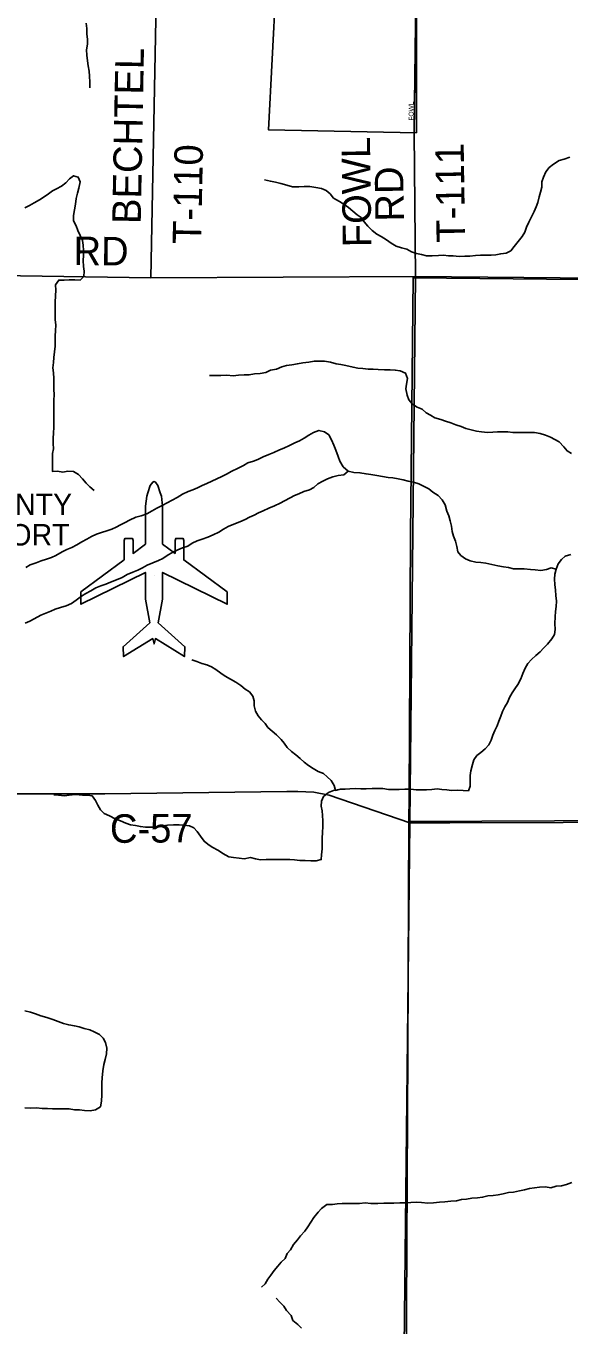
# Model space of a CAD drawing. Extents: x 1857828 to 2277390, y 930619 to 1324581.
# Drawn here: x 2056259 to 2061968, y 1210395 to 1224059 of the extents above; entities that cross this region are included whole.
import ezdxf

# ---------------------------------------------------------------- set-up
doc = ezdxf.new("R2010")
doc.units = 0
for name, color, linetype in [('GM_X_Airport_Class_2', 7, 'Continuous'), ('GM_X_Airport_Location_Class_2', 7, 'Continuous'), ('GM_X_Airport_Text_Class_2', 7, 'Continuous'), ('GM_X_City_Street', 7, 'Continuous'), ('GM_X_City_Street_Text', 7, 'Continuous'), ('GM_X_Corporation', 7, 'Continuous'), ('GM_X_County_Road', 7, 'Continuous'), ('GM_X_County_Road_Text', 7, 'Continuous'), ('GM_X_Minor_River', 7, 'Continuous'), ('GM_X_Section', 7, 'Continuous'), ('GM_X_Township', 7, 'Continuous'), ('GM_X_Township_Road', 7, 'Continuous'), ('GM_X_Township_Road_Text', 7, 'Continuous')]:
    doc.layers.add(name, color=color, linetype=linetype)

msp = doc.modelspace()

# ---------------------------------------------------------------- linework, layer by layer
at = {"layer": 'GM_X_Airport_Class_2'}
msp.add_lwpolyline([(2057292, 1218448), (2056836, 1218111), (2056836, 1217981), (2057515, 1218316), (2057515, 1218034), (2057560, 1217785), (2057280, 1217534), (2057285, 1217431), (2057591, 1217620), (2057605, 1217565), (2057619, 1217620), (2057925, 1217431), (2057929, 1217534), (2057650, 1217785), (2057695, 1218034), (2057695, 1218316), (2058374, 1217981), (2058374, 1218111), (2057918, 1218448), (2057918, 1218650), (2057911, 1218674), (2057833, 1218674), (2057826, 1218650), (2057826, 1218516), (2057695, 1218613), (2057695, 1218613), (2057695, 1219011), (2057682, 1219116), (2057671, 1219153), (2057644, 1219230), (2057619, 1219264), (2057605, 1219270), (2057591, 1219264), (2057566, 1219230), (2057539, 1219153), (2057528, 1219116), (2057515, 1219011), (2057515, 1218613), (2057384, 1218516), (2057384, 1218650), (2057377, 1218674), (2057299, 1218674), (2057292, 1218650)], close=True, dxfattribs=at)
at = {"layer": 'GM_X_Airport_Location_Class_2'}
msp.add_line((2057605, 1218287), (2057605, 1218287), dxfattribs=at)
at = {"layer": 'GM_X_City_Street'}
msp.add_lwpolyline([(2060339, 1222974), (2060377, 1225997), (2060390, 1226015)], dxfattribs=at)
at = {"layer": 'GM_X_Corporation'}
msp.add_lwpolyline([(2060364, 1224534), (2060364, 1222938), (2058808, 1222969), (2058885, 1224457)], dxfattribs=at)
at = {"layer": 'GM_X_County_Road'}
for points in [[(2052543, 1221491), (2057571, 1221413), (2060354, 1221425)], [(2060354, 1221425), (2063013, 1221403)], [(2046506, 1216127), (2048640, 1216054), (2049006, 1216051), (2049292, 1216047), (2049598, 1216044), (2049915, 1216043), (2050453, 1216041), (2050976, 1216041), (2052033, 1216054), (2055846, 1215989), (2056808, 1215987), (2057088, 1215987), (2059001, 1216013), (2059118, 1216013), (2059284, 1216005), (2059445, 1215973), (2060294, 1215683), (2060319, 1215683)], [(2060319, 1215683), (2060715, 1215683), (2064289, 1215694), (2067474, 1215668), (2070111, 1215714), (2071694, 1215684), (2072330, 1215682)]]:
    msp.add_lwpolyline(points, dxfattribs=at)
at = {"layer": 'GM_X_Minor_River'}
for points in [[(2056893, 1224089), (2056900, 1224033), (2056900, 1223972), (2056904, 1223922), (2056904, 1223868), (2056896, 1223808), (2056900, 1223752), (2056906, 1223692), (2056914, 1223642), (2056923, 1223584), (2056927, 1223533), (2056929, 1223469), (2056931, 1223409)], [(2061976, 1222680), (2061918, 1222661), (2061864, 1222645), (2061806, 1222607), (2061758, 1222571), (2061725, 1222525), (2061699, 1222469), (2061683, 1222421), (2061681, 1222365), (2061668, 1222313), (2061654, 1222263), (2061640, 1222205), (2061624, 1222157), (2061600, 1222111), (2061577, 1222061), (2061547, 1221999), (2061521, 1221943), (2061503, 1221891), (2061474, 1221847), (2061432, 1221793), (2061392, 1221743), (2061356, 1221697), (2061306, 1221671), (2061250, 1221665), (2061200, 1221655), (2061150, 1221652), (2061100, 1221650), (2061038, 1221652), (2060984, 1221648), (2060924, 1221641), (2060872, 1221639), (2060814, 1221637), (2060750, 1221642), (2060700, 1221644), (2060648, 1221652), (2060596, 1221648), (2060530, 1221645), (2060468, 1221645), (2060416, 1221657), (2060364, 1221669), (2060312, 1221686)], [(2056246, 1222148), (2056296, 1222171), (2056346, 1222199), (2056400, 1222231), (2056450, 1222265), (2056494, 1222295), (2056536, 1222325), (2056580, 1222349), (2056631, 1222376), (2056677, 1222412), (2056717, 1222452), (2056759, 1222486), (2056809, 1222472), (2056829, 1222420), (2056816, 1222355), (2056802, 1222303), (2056788, 1222247), (2056778, 1222187), (2056767, 1222127), (2056757, 1222067), (2056757, 1222011), (2056785, 1221959), (2056805, 1221910), (2056830, 1221856), (2056852, 1221806), (2056860, 1221756), (2056862, 1221698), (2056863, 1221648), (2056859, 1221593), (2056863, 1221533), (2056869, 1221481), (2056867, 1221427), (2056828, 1221389), (2056774, 1221391), (2056714, 1221390), (2056660, 1221386), (2056604, 1221388), (2056570, 1221340), (2056572, 1221282), (2056568, 1221224), (2056565, 1221158), (2056565, 1221100), (2056567, 1221033), (2056567, 1220971), (2056572, 1220919), (2056570, 1220855), (2056564, 1220801), (2056566, 1220749), (2056565, 1220693), (2056559, 1220633), (2056553, 1220574), (2056547, 1220524), (2056540, 1220466), (2056548, 1220412), (2056550, 1220354), (2056552, 1220302), (2056550, 1220240), (2056555, 1220185), (2056551, 1220123), (2056551, 1220069), (2056553, 1220011), (2056552, 1219957), (2056550, 1219893), (2056550, 1219839), (2056548, 1219783), (2056543, 1219722)], [(2060312, 1221686), (2060264, 1221712), (2060206, 1221728), (2060150, 1221745), (2060098, 1221777), (2060048, 1221813), (2059992, 1221846), (2059949, 1221872), (2059897, 1221910), (2059853, 1221954), (2059815, 1222001), (2059783, 1222045), (2059739, 1222073), (2059694, 1222112), (2059650, 1222152), (2059604, 1222182), (2059556, 1222216), (2059492, 1222251), (2059458, 1222295), (2059416, 1222331), (2059365, 1222352), (2059307, 1222360), (2059243, 1222372), (2059185, 1222371), (2059129, 1222369), (2059061, 1222369), (2059001, 1222387), (2058937, 1222402), (2058881, 1222416), (2058829, 1222428), (2058767, 1222443)], [(2061995, 1219565), (2061947, 1219593), (2061913, 1219635), (2061863, 1219688), (2061818, 1219714), (2061774, 1219738), (2061722, 1219759), (2061666, 1219775), (2061604, 1219787), (2061548, 1219787), (2061494, 1219788), (2061438, 1219788), (2061378, 1219786), (2061326, 1219792), (2061274, 1219793), (2061216, 1219795), (2061166, 1219791), (2061110, 1219787), (2061048, 1219792), (2060996, 1219800), (2060940, 1219814), (2060882, 1219829), (2060834, 1219849), (2060778, 1219867), (2060726, 1219887), (2060670, 1219906), (2060622, 1219924), (2060558, 1219940), (2060513, 1219967), (2060465, 1219993), (2060423, 1220033), (2060373, 1220053), (2060323, 1220086), (2060285, 1220130), (2060265, 1220180), (2060254, 1220244), (2060258, 1220295), (2060270, 1220353), (2060248, 1220411), (2060194, 1220433), (2060141, 1220443), (2060087, 1220446), (2060027, 1220446), (2059963, 1220450), (2059909, 1220451), (2059855, 1220453), (2059799, 1220459), (2059749, 1220463), (2059697, 1220472), (2059621, 1220492), (2059569, 1220500), (2059519, 1220509), (2059459, 1220525), (2059397, 1220537), (2059345, 1220537), (2059289, 1220536), (2059231, 1220526), (2059171, 1220518), (2059113, 1220510), (2059055, 1220499), (2058997, 1220489), (2058947, 1220475), (2058893, 1220453), (2058830, 1220440), (2058782, 1220418), (2058720, 1220406), (2058660, 1220402), (2058606, 1220394), (2058554, 1220393), (2058494, 1220389), (2058436, 1220383), (2058370, 1220388), (2058306, 1220386), (2058238, 1220386), (2058188, 1220384)], [(2059646, 1219381), (2059592, 1219426), (2059560, 1219486), (2059541, 1219536), (2059517, 1219600), (2059497, 1219655), (2059471, 1219709), (2059442, 1219761), (2059396, 1219793), (2059338, 1219808), (2059282, 1219786), (2059234, 1219758), (2059183, 1219726), (2059133, 1219698), (2059085, 1219677), (2059029, 1219651), (2058971, 1219623), (2058923, 1219605), (2058863, 1219577), (2058811, 1219554), (2058751, 1219530), (2058698, 1219504), (2058650, 1219484), (2058592, 1219468), (2058544, 1219438), (2058484, 1219409), (2058422, 1219379), (2058368, 1219349), (2058318, 1219325), (2058266, 1219299), (2058212, 1219274), (2058159, 1219250), (2058111, 1219228), (2058063, 1219206), (2058013, 1219184), (2057965, 1219165), (2057905, 1219139), (2057847, 1219105), (2057795, 1219077), (2057743, 1219049), (2057690, 1219019), (2057636, 1218992), (2057586, 1218962), (2057528, 1218932), (2057468, 1218912), (2057412, 1218898), (2057346, 1218865), (2057300, 1218841), (2057252, 1218817), (2057207, 1218793), (2057161, 1218771), (2057107, 1218752), (2057053, 1218736), (2056999, 1218718), (2056947, 1218692), (2056899, 1218664), (2056847, 1218636), (2056793, 1218607), (2056739, 1218579), (2056688, 1218557), (2056638, 1218531), (2056574, 1218495), (2056526, 1218472), (2056476, 1218454), (2056420, 1218436), (2056366, 1218418), (2056302, 1218396), (2056258, 1218367)], [(2056543, 1219722), (2056543, 1219670), (2056547, 1219616), (2056537, 1219566), (2056538, 1219508), (2056538, 1219440), (2056538, 1219376), (2056590, 1219379), (2056646, 1219371), (2056700, 1219381), (2056758, 1219377), (2056810, 1219346), (2056852, 1219298), (2056891, 1219254), (2056929, 1219215), (2056977, 1219177)], [(2059646, 1219381), (2059602, 1219341), (2059542, 1219336), (2059484, 1219320), (2059430, 1219298), (2059378, 1219276), (2059327, 1219246), (2059285, 1219209), (2059239, 1219183), (2059181, 1219165), (2059127, 1219143), (2059081, 1219123), (2059035, 1219099), (2058977, 1219068), (2058931, 1219044), (2058872, 1219016), (2058812, 1218990), (2058754, 1218964), (2058704, 1218941), (2058658, 1218919), (2058610, 1218895), (2058562, 1218871), (2058506, 1218847), (2058444, 1218824), (2058386, 1218798), (2058337, 1218770), (2058285, 1218738), (2058227, 1218710), (2058169, 1218686), (2058111, 1218667), (2058057, 1218647), (2058005, 1218623), (2057959, 1218593), (2057905, 1218573), (2057856, 1218552), (2057804, 1218528), (2057744, 1218494), (2057698, 1218462), (2057652, 1218442), (2057592, 1218418), (2057534, 1218393), (2057482, 1218365), (2057434, 1218339), (2057381, 1218317), (2057323, 1218293), (2057269, 1218264), (2057209, 1218238), (2057149, 1218212), (2057097, 1218194), (2057047, 1218174), (2056993, 1218153), (2056941, 1218123), (2056887, 1218093), (2056842, 1218067), (2056786, 1218025), (2056736, 1217989), (2056680, 1217964), (2056622, 1217948), (2056566, 1217930), (2056520, 1217908), (2056466, 1217888), (2056416, 1217867), (2056345, 1217829), (2056299, 1217805), (2056249, 1217783)], [(2061832, 1218349), (2061782, 1218363), (2061732, 1218347), (2061672, 1218337), (2061612, 1218342), (2061562, 1218348), (2061498, 1218352), (2061446, 1218354), (2061384, 1218355), (2061330, 1218369), (2061278, 1218375), (2061218, 1218386), (2061158, 1218398), (2061092, 1218414), (2061040, 1218419), (2060990, 1218425), (2060928, 1218439), (2060878, 1218459), (2060832, 1218492), (2060798, 1218532), (2060787, 1218590), (2060773, 1218646), (2060755, 1218696), (2060739, 1218745), (2060732, 1218801), (2060718, 1218859), (2060704, 1218911), (2060682, 1218961), (2060665, 1219026), (2060635, 1219078), (2060591, 1219126), (2060535, 1219161), (2060493, 1219195), (2060439, 1219223), (2060389, 1219247), (2060334, 1219266), (2060278, 1219276), (2060224, 1219290), (2060170, 1219301), (2060116, 1219309), (2060066, 1219315), (2060008, 1219323), (2059946, 1219336), (2059884, 1219344), (2059834, 1219352), (2059770, 1219363), (2059704, 1219367), (2059646, 1219381)], [(2061986, 1218504), (2061928, 1218487), (2061890, 1218453), (2061854, 1218407), (2061832, 1218349), (2061818, 1218297), (2061817, 1218244), (2061819, 1218190), (2061825, 1218130), (2061829, 1218074), (2061836, 1218012), (2061832, 1217956), (2061826, 1217904), (2061824, 1217850), (2061819, 1217779), (2061823, 1217715), (2061815, 1217663), (2061789, 1217619), (2061742, 1217561), (2061700, 1217519), (2061664, 1217481), (2061618, 1217442), (2061572, 1217402), (2061534, 1217360), (2061507, 1217310), (2061483, 1217252), (2061461, 1217196), (2061431, 1217138), (2061398, 1217092), (2061370, 1217050), (2061342, 1217000), (2061320, 1216950), (2061294, 1216904), (2061267, 1216854), (2061251, 1216804), (2061231, 1216752), (2061211, 1216704), (2061189, 1216656), (2061168, 1216604), (2061150, 1216552), (2061126, 1216504), (2061086, 1216460), (2061040, 1216424), (2060999, 1216390), (2060969, 1216346), (2060953, 1216298), (2060937, 1216232), (2060929, 1216180), (2060930, 1216120), (2060930, 1216069), (2060910, 1216021), (2060856, 1216022), (2060796, 1216026), (2060732, 1216024), (2060682, 1216029), (2060632, 1216035), (2060582, 1216041), (2060524, 1216033), (2060470, 1216032), (2060416, 1216032), (2060362, 1216032), (2060306, 1216038), (2060242, 1216039), (2060182, 1216035), (2060126, 1216033), (2060070, 1216035), (2060010, 1216044), (2059958, 1216046), (2059900, 1216046), (2059836, 1216042), (2059778, 1216041), (2059724, 1216043), (2059664, 1216041), (2059614, 1216038), (2059564, 1216036)], [(2059564, 1216036), (2059514, 1216024), (2059500, 1216076), (2059466, 1216128), (2059424, 1216169), (2059385, 1216201), (2059331, 1216225), (2059279, 1216254), (2059229, 1216286), (2059183, 1216322), (2059143, 1216360), (2059095, 1216399), (2059050, 1216435), (2059006, 1216475), (2058974, 1216522), (2058940, 1216560), (2058894, 1216608), (2058848, 1216648), (2058803, 1216687), (2058773, 1216727), (2058735, 1216765), (2058701, 1216808), (2058673, 1216858), (2058658, 1216914), (2058656, 1216966), (2058644, 1217016), (2058608, 1217059), (2058564, 1217089), (2058516, 1217127), (2058465, 1217163), (2058409, 1217194), (2058353, 1217224), (2058309, 1217256), (2058255, 1217295), (2058209, 1217323), (2058161, 1217343), (2058107, 1217360), (2058056, 1217380), (2058002, 1217398)], [(2059564, 1216036), (2059492, 1216022), (2059438, 1216004), (2059388, 1215962), (2059365, 1215912), (2059363, 1215860), (2059373, 1215810), (2059377, 1215760), (2059379, 1215704), (2059380, 1215644), (2059376, 1215582), (2059374, 1215523), (2059374, 1215469), (2059373, 1215409), (2059365, 1215347), (2059363, 1215297), (2059311, 1215283), (2059255, 1215283), (2059195, 1215288), (2059139, 1215288), (2059083, 1215294), (2059033, 1215298), (2058969, 1215297), (2058909, 1215297), (2058847, 1215297), (2058783, 1215298), (2058723, 1215296), (2058673, 1215306), (2058619, 1215318), (2058553, 1215307), (2058501, 1215313), (2058441, 1215321), (2058391, 1215327), (2058329, 1215360), (2058281, 1215394), (2058217, 1215429), (2058171, 1215461), (2058132, 1215491), (2058094, 1215543), (2058060, 1215594), (2058024, 1215630), (2057978, 1215654), (2057918, 1215660), (2057868, 1215663), (2057810, 1215663), (2057746, 1215659), (2057686, 1215648), (2057630, 1215638), (2057574, 1215638), (2057514, 1215640), (2057462, 1215645), (2057410, 1215655), (2057358, 1215663), (2057310, 1215679), (2057254, 1215706), (2057195, 1215726), (2057135, 1215756), (2057079, 1215783), (2057043, 1215819), (2057013, 1215871), (2056991, 1215917), (2056956, 1215966), (2056906, 1215974), (2056852, 1215976), (2056778, 1215980), (2056714, 1215975), (2056662, 1215969), (2056602, 1215975), (2056550, 1215978)], [(2056246, 1212689), (2056308, 1212685), (2056368, 1212687), (2056430, 1212682), (2056484, 1212682), (2056538, 1212678), (2056598, 1212678), (2056660, 1212677), (2056714, 1212677), (2056768, 1212669), (2056820, 1212667), (2056874, 1212660), (2056932, 1212658), (2056990, 1212668), (2057042, 1212700), (2057052, 1212758), (2057056, 1212824), (2057057, 1212886), (2057055, 1212952), (2057059, 1213002), (2057065, 1213078), (2057078, 1213142), (2057092, 1213197), (2057104, 1213257), (2057108, 1213317), (2057093, 1213375), (2057071, 1213421), (2057033, 1213459), (2056977, 1213486), (2056929, 1213508), (2056871, 1213522), (2056817, 1213541), (2056767, 1213549), (2056709, 1213559), (2056654, 1213573), (2056596, 1213594), (2056540, 1213616), (2056478, 1213638), (2056416, 1213657), (2056360, 1213675), (2056306, 1213693), (2056248, 1213708)], [(2061997, 1211903), (2061941, 1211883), (2061888, 1211867), (2061834, 1211865), (2061776, 1211848), (2061720, 1211858), (2061656, 1211856), (2061606, 1211848), (2061552, 1211839)], [(2061552, 1211839), (2061500, 1211827), (2061446, 1211815), (2061386, 1211803), (2061330, 1211798), (2061274, 1211784), (2061222, 1211774), (2061172, 1211768), (2061116, 1211763), (2061060, 1211749), (2061006, 1211743), (2060946, 1211739), (2060890, 1211730), (2060836, 1211724), (2060786, 1211710), (2060724, 1211706), (2060664, 1211701), (2060608, 1211697), (2060542, 1211691), (2060484, 1211687), (2060416, 1211694), (2060364, 1211696), (2060304, 1211694), (2060246, 1211690), (2060190, 1211689), (2060126, 1211687), (2060074, 1211687), (2060022, 1211685), (2059958, 1211684), (2059886, 1211682), (2059826, 1211690), (2059764, 1211683), (2059708, 1211683), (2059638, 1211683), (2059582, 1211683), (2059532, 1211680), (2059482, 1211672), (2059420, 1211672), (2059365, 1211630), (2059331, 1211592), (2059285, 1211535), (2059255, 1211487), (2059223, 1211437), (2059190, 1211393), (2059146, 1211343), (2059112, 1211301), (2059072, 1211253), (2059038, 1211197), (2059005, 1211157), (2058983, 1211103), (2058943, 1211067), (2058905, 1211023), (2058867, 1210977), (2058832, 1210931), (2058802, 1210887), (2058772, 1210839), (2058734, 1210803)], [(2059156, 1210372), (2059118, 1210411), (2059064, 1210453), (2059047, 1210505), (2058999, 1210558), (2058969, 1210602), (2058927, 1210644), (2058889, 1210688)]]:
    msp.add_lwpolyline(points, dxfattribs=at)
at = {"layer": 'GM_X_Section'}
for points in [[(2065236, 1221364), (2065718, 1221358), (2065650, 1215721), (2060285, 1215697), (2060286, 1215959), (2060300, 1218715), (2060328, 1221413)], [(2060285, 1215697), (2065650, 1215721), (2065594, 1209969), (2060255, 1209971), (2060255, 1209988), (2060259, 1210570), (2060274, 1213273)]]:
    msp.add_lwpolyline(points, close=True, dxfattribs=at)
at = {"layer": 'GM_X_Township'}
for points in [[(2060647, 1243760), (2060635, 1243186), (2060633, 1243086), (2060628, 1242873), (2060601, 1241567), (2060572, 1240155), (2060516, 1235516), (2060506, 1234916), (2060504, 1234835), (2060494, 1234234), (2060445, 1231137), (2060427, 1229155), (2060377, 1225997), (2060339, 1222935), (2060354, 1221425), (2057571, 1221413), (2052543, 1221491), (2047129, 1221472), (2042623, 1221498), (2039744, 1221515), (2035913, 1221537)], [(2086907, 1225123), (2086885, 1221291), (2086459, 1221291), (2084361, 1221334), (2078877, 1221358), (2077897, 1221356), (2076980, 1221348), (2076348, 1221342), (2075410, 1221333), (2074869, 1221327), (2074729, 1221326), (2072926, 1221321), (2071560, 1221318), (2067771, 1221365), (2063493, 1221407), (2063013, 1221403), (2060354, 1221425), (2060339, 1222935), (2060377, 1225997)], [(2032548, 1208287), (2032612, 1216299), (2032643, 1220072), (2032655, 1221559), (2034660, 1221545), (2035913, 1221537), (2039744, 1221515), (2042623, 1221498), (2047129, 1221472), (2052543, 1221491), (2057571, 1221413), (2060354, 1221425), (2060294, 1215683), (2060204, 1207259)], [(2060204, 1207259), (2060294, 1215683), (2060354, 1221425), (2063013, 1221403), (2063493, 1221407), (2067771, 1221365), (2071560, 1221318)]]:
    msp.add_lwpolyline(points, dxfattribs=at)
at = {"layer": 'GM_X_Township_Road'}
for points in [[(2057571, 1221413), (2057697, 1227931)], [(2060354, 1221425), (2060339, 1222935), (2060339, 1222974)]]:
    msp.add_lwpolyline(points, dxfattribs=at)

# ---------------------------------------------------------------- texts
at = {"layer": 'GM_X_Airport_Text_Class_2'}
for s, p in [('LORAIN COUNTY', (2054270, 1218920)), ('REGIONAL AIRPORT', (2053742, 1218599))]:
    msp.add_text(s, height=225, rotation=0, dxfattribs=at).set_placement(p)
at = {"layer": 'GM_X_City_Street_Text'}
msp.add_text('FOWL', height=50, rotation=90, dxfattribs=at).set_placement((2060333, 1223065))
at = {"layer": 'GM_X_County_Road_Text'}
for s, rotation, p in [('RD', 359.5064, (2056757, 1221546)), ('C-57', 0.3429, (2057142, 1215473))]:
    msp.add_text(s, height=300, rotation=rotation, dxfattribs=at).set_placement(p)
at = {"layer": 'GM_X_Township_Road_Text'}
for s, rotation, p in [('BECHTEL', 88.9306, (2057465, 1221976)), ('T-110', 88.8762, (2058100, 1221765)), ('FOWL', 90.7279, (2059890, 1221736)), ('T-111', 90.8421, (2060876, 1221783)), ('RD', 90.9873, (2060233, 1222006))]:
    msp.add_text(s, height=300, rotation=rotation, dxfattribs=at).set_placement(p)

doc.saveas('drawing.dxf')
